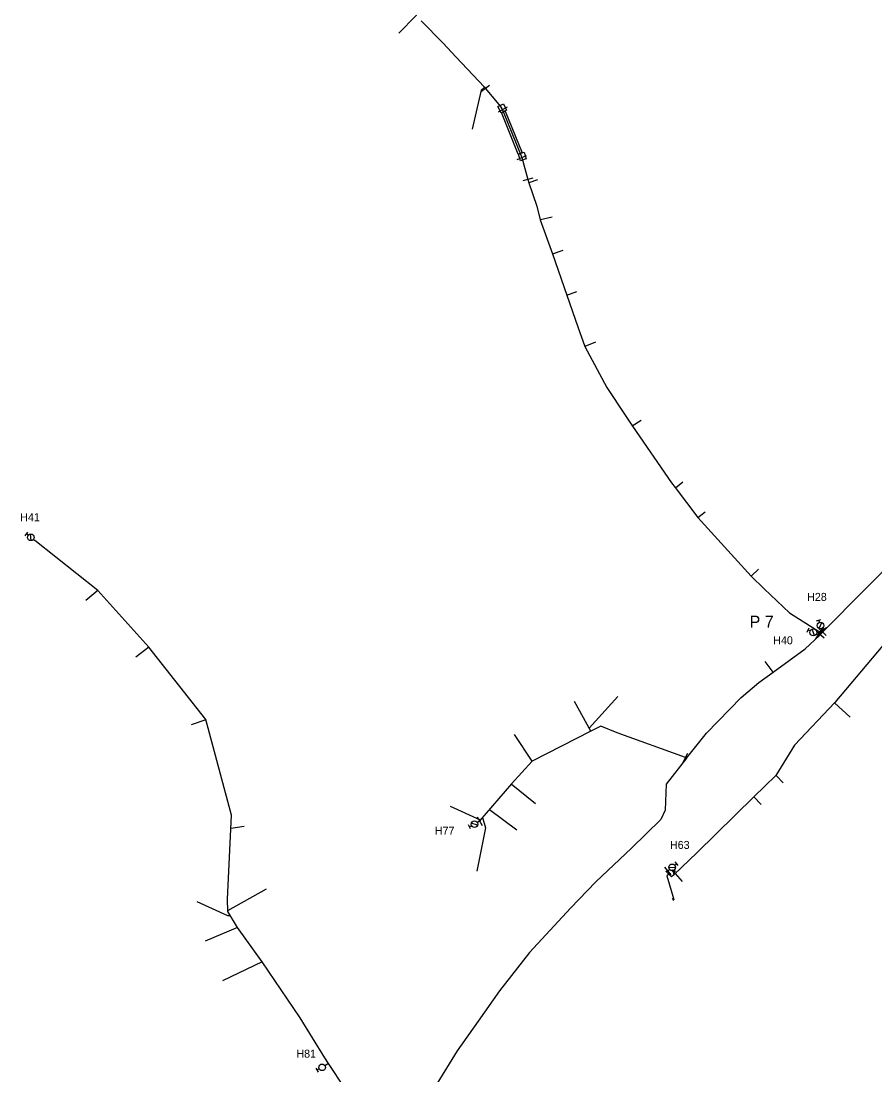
# Model space of a CAD drawing. Extents: x -548873 to -538270, y -1201997 to -1192514.
# Drawn here: x -547520.2 to -547306.8, y -1195753.9 to -1195490.5 of the extents above; entities that cross this region are included whole.
import ezdxf

# ---------------------------------------------------------------- set-up
doc = ezdxf.new("R2010")
doc.units = 0
for name, color, linetype in [('KN_HRAN_STÁTNÍ', 7, 'Continuous'), ('KN_PARC_Č', 7, 'Continuous'), ('KN_VKP_HRAN_SPORNÁ', 7, 'Continuous'), ('PK_PARC_Čv', 7, 'Continuous'), ('Vrstva 29', 7, 'Continuous'), ('Vrstva 37', 7, 'Continuous'), ('Vrstva 39', 7, 'Continuous')]:
    doc.layers.add(name, color=color, linetype=linetype)

# ---------------------------------------------------------------- blocks, each defined once
blk = doc.blocks.new('160')
at = {"layer": 'KN_HRAN_STÁTNÍ'}
blk.add_circle((0, 0), 0.0458, dxfattribs=at)
blk = doc.blocks.new('147')
at = {"layer": 'KN_HRAN_STÁTNÍ'}
blk.add_line((0, 1.27), (0, -1.27), dxfattribs=at)
blk = doc.blocks.new('133')
at = {"layer": 'KN_HRAN_STÁTNÍ'}
for p, q in [((0.28, 0), (0, 0)), ((0.54, 0.58), (1.7, -0.58)), ((1.94, 0), (2.52, 0)), ((2.52, 0.58), (2.52, -0.58))]:
    blk.add_line(p, q, dxfattribs=at)
blk.add_circle((1.11, 0), 0.825, dxfattribs=at)
blk = doc.blocks.new('132')
at = {"layer": 'KN_HRAN_STÁTNÍ'}
for p, q in [((0.3, 0), (0, 0)), ((1.96, 0), (2.52, 0)), ((2.52, 0.58), (2.52, -0.58))]:
    blk.add_line(p, q, dxfattribs=at)
blk.add_circle((1.13, 0.01), 0.825, dxfattribs=at)
blk = doc.blocks.new('150')
at = {"layer": 'KN_HRAN_STÁTNÍ'}
blk.add_line((0, 1.27), (0, -1.27), dxfattribs=at)
blk = doc.blocks.new('128')
at = {"layer": 'KN_HRAN_STÁTNÍ'}
for p, q in [((-0.19, 1.06), (-0.43, 1.15)), ((-0.36, 0.84), (-0.19, 1.06)), ((-0.19, 1.06), (-0.02, 1.25)), ((-0.19, 1.06), (0, 0)), ((0.05, 0.95), (-0.19, 1.06)), ((-0.1, 1), (0.41, 0.91)), ((-0.07, 0.82), (0.17, 0.96)), ((0.17, 0.96), (-0.02, 1.13)), ((0.17, 0.96), (0, 0)), ((0.19, 1.21), (0.17, 0.96)), ((0.17, 0.96), (0.38, 1.08)), ((0.36, 0.77), (0.17, 0.96))]:
    blk.add_line(p, q, dxfattribs=at)

msp = doc.modelspace()

# ---------------------------------------------------------------- linework, layer by layer
at = {"layer": 'KN_PARC_Č'}
for points in [[(-547421.368, -1195489.122), (-547421.49, -1195489.23), (-547425.759, -1195493.564)], [(-547404.348, -1195507.003), (-547404.44, -1195507.09), (-547405.167, -1195507.776), (-547407.449, -1195517.535)], [(-547393.308, -1195530.92), (-547393.19, -1195530.89), (-547391.015, -1195530.156)], [(-547390.473, -1195540.168), (-547390.35, -1195540.14), (-547387.475, -1195539.42)], [(-547387.323, -1195548.662), (-547384.692, -1195547.782)], [(-547383.738, -1195558.995), (-547381.305, -1195558.142)], [(-547379.307, -1195571.831), (-547379.16, -1195571.78), (-547376.533, -1195570.701)], [(-547367.407, -1195591.73), (-547365.218, -1195590.303)], [(-547356.654, -1195607.161), (-547354.823, -1195605.7)], [(-547351.028, -1195614.592), (-547349.206, -1195613.219)], [(-547337.739, -1195629.251), (-547335.853, -1195627.531)], [(-547500.975, -1195632.852), (-547504.001, -1195635.361)], [(-547488.22, -1195647.052), (-547491.504, -1195649.479)], [(-547332.224, -1195653.223), (-547334.189, -1195650.617)], [(-547377.778, -1195668.026), (-547381.876, -1195660.553)], [(-547378.208, -1195667.242), (-547371.04, -1195659.312)], [(-547316.9, -1195660.93), (-547312.995, -1195664.495)], [(-547474.007, -1195665.163), (-547477.666, -1195666.391)], [(-547392.404, -1195675.474), (-547396.862, -1195668.814)], [(-547331.495, -1195679.06), (-547329.695, -1195680.901)], [(-547397.645, -1195681.202), (-547391.615, -1195686.121)], [(-547337.038, -1195684.445), (-547335.245, -1195686.308)], [(-547405.354, -1195690.223), (-547412.826, -1195686.829)], [(-547404.824, -1195689.603), (-547404.093, -1195692.207), (-547406.29, -1195702.973)], [(-547403.128, -1195687.618), (-547396.236, -1195692.664)], [(-547467.746, -1195692.252), (-547464.4, -1195691.77)], [(-547358.294, -1195703.731), (-547358.766, -1195704.195), (-547357.002, -1195710.113)], [(-547356.708, -1195703.598), (-547354.916, -1195705.609)], [(-547468.498, -1195712.843), (-547458.817, -1195707.457)], [(-547467.871, -1195714.136), (-547468.499, -1195714.186), (-547476.15, -1195710.63)], [(-547357.124, -1195709.705), (-547357.491, -1195710.009)], [(-547357.066, -1195709.898), (-547357.278, -1195710.35)], [(-547466.059, -1195717.114), (-547474.163, -1195720.528)], [(-547459.879, -1195725.68), (-547469.82, -1195730.418)]]:
    msp.add_lwpolyline(points, dxfattribs=at)
at = {"layer": 'KN_VKP_HRAN_SPORNÁ'}
for points in [[(-547420.18, -1195490.46), (-547414.68, -1195496.05), (-547411.499, -1195499.421), (-547404.35, -1195507), (-547404.08, -1195507.37)], [(-547404.08, -1195507.37), (-547400.46, -1195511.78), (-547399.83, -1195512.67)], [(-547399.83, -1195512.67), (-547396.278, -1195521.521), (-547395.03, -1195524.63)], [(-547395.03, -1195524.63), (-547393.52, -1195530.09)], [(-547393.52, -1195530.09), (-547393.3, -1195530.95), (-547391.26, -1195536.75), (-547390.47, -1195540.18), (-547387.32, -1195548.67), (-547383.74, -1195558.99), (-547380.993, -1195566.947), (-547379.3, -1195571.85), (-547373.75, -1195582.08), (-547369.199, -1195589.003), (-547367.4, -1195591.74), (-547357.64, -1195605.93), (-547356.67, -1195607.14), (-547351.03, -1195614.59), (-547343.58, -1195622.85), (-547337.74, -1195629.25), (-547334.43, -1195632.46), (-547328.16, -1195638.43), (-547321.548, -1195642.574), (-547320.39, -1195643.3)], [(-547241.246, -1195569.957), (-547259.588, -1195592.568), (-547270.51, -1195606.032), (-547278.725, -1195615.639), (-547291.147, -1195630.416), (-547304.795, -1195646.608), (-547316.823, -1195660.848), (-547326.873, -1195671.491), (-547331.512, -1195679.088), (-547337.016, -1195684.424), (-547351.223, -1195698.329), (-547357.069, -1195703.944)], [(-547319.87, -1195643.25), (-547319.38, -1195642.78), (-547300.1, -1195623.31), (-547296.04, -1195618.93), (-547293.43, -1195615.64)], [(-547425.785, -1195772.759), (-547433.342, -1195767.71), (-547439.235, -1195757.255), (-547443.312, -1195751.099), (-547444.279, -1195749.64), (-547450.389, -1195739.691), (-547459.879, -1195725.68), (-547466.059, -1195717.114), (-547468.493, -1195713.113), (-547468.55, -1195710.024), (-547467.599, -1195689.001), (-547474.02, -1195665.116), (-547488.253, -1195647.01), (-547500.937, -1195632.883), (-547516.701, -1195620.349), (-547516.745, -1195620.314)], [(-547353.907, -1195674.777), (-547348.862, -1195668.535), (-547340.213, -1195659.581), (-547335.828, -1195655.833), (-547332.223, -1195653.222), (-547324.245, -1195647.444), (-547320.669, -1195644.126), (-547320.44, -1195643.86)], [(-547320.44, -1195643.86), (-547320.091, -1195643.487)], [(-547320.39, -1195643.3), (-547320.091, -1195643.487)], [(-547320.091, -1195643.487), (-547319.87, -1195643.25)], [(-547354.157, -1195674.632), (-547371.167, -1195668.434), (-547375.271, -1195666.75), (-547377.778, -1195668.026), (-547392.405, -1195675.475), (-547392.427, -1195675.486), (-547397.637, -1195681.193), (-547405.479, -1195690.369)], [(-547353.907, -1195674.777), (-547358.947, -1195681.231), (-547359.171, -1195687.793), (-547360.282, -1195690.048), (-547367.646, -1195697.265), (-547376.495, -1195705.645), (-547382.898, -1195712.235), (-547393.089, -1195723.345), (-547400.573, -1195732.935), (-547405.899, -1195740.503), (-547411.174, -1195747.949), (-547417.586, -1195758.304), (-547425.386, -1195772.82)], [(-547353.907, -1195674.777), (-547354.157, -1195674.632)], [(-547357.069, -1195703.944), (-547357.605, -1195704.459), (-547358.916, -1195703.075)]]:
    msp.add_lwpolyline(points, dxfattribs=at)
at = {"layer": 'PK_PARC_Čv'}
for points in [[(-547400.978, -1195511.838), (-547399.63, -1195511.18), (-547398.83, -1195512.82), (-547400.178, -1195513.478), (-547400.978, -1195511.838)], [(-547395.876, -1195523.767), (-547394.45, -1195523.3), (-547393.9, -1195524.98), (-547395.326, -1195525.447), (-547395.876, -1195523.767)], [(-547516.745, -1195620.314), (-547516.825, -1195620.25)], [(-547319.711, -1195643.098), (-547319.93, -1195642.87), (-547320.01, -1195642.63)], [(-547320.67, -1195644.127), (-547320.906, -1195643.864), (-547321.12, -1195643.784)], [(-547405.479, -1195690.369), (-547405.554, -1195690.502), (-547405.899, -1195690.693)], [(-547358.819, -1195703.177), (-547358.31, -1195702.755)], [(-547443.312, -1195751.099), (-547443.972, -1195751.466)]]:
    msp.add_lwpolyline(points, dxfattribs=at)
at = {"layer": 'Vrstva 37'}
msp.add_lwpolyline([(-547399.152, -1195513.017), (-547394.97, -1195523.436), (-547395.898, -1195523.808), (-547400.08, -1195513.389), (-547399.152, -1195513.017)], dxfattribs=at)

# ---------------------------------------------------------------- block references
at = {"layer": 'PK_PARC_Čv'}
for name, p, xscale, yscale, rotation in [('133', (-547516.825, -1195620.25), 1.000000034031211, 1.0000000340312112, 141.99999959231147), ('133', (-547320.01, -1195642.63), 0.999999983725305, 0.999999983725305, 109.00000122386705), ('133', (-547321.12, -1195643.784), 1.0296949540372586, 1.0296949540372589, 155.86620948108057), ('150', (-547320.906, -1195643.864), 0.9999999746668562, 0.999999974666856, -34.00000045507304), ('150', (-547319.93, -1195642.87), 0.9999999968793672, 0.9999999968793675, -57.99999972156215), ('133', (-547405.899, -1195690.693), 1.0037042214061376, 1.0037042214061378, -150.62079160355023), ('150', (-547405.555, -1195690.503), 1.0037042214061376, 1.0037042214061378, 29.379208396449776), ('133', (-547358.31, -1195702.755), 1.0000000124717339, 1.0000000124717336, 40.00000131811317), ('150', (-547358.581, -1195702.98), 1.0000000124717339, 1.0000000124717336, 40.00000131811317), ('132', (-547443.972, -1195751.466), 0.9999999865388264, 0.9999999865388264, -149.99999955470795)]:
    msp.add_blockref(name, p, dxfattribs=dict(at, xscale=xscale, yscale=yscale, rotation=rotation))
at = {"layer": 'Vrstva 29'}
for name, p, xscale, yscale, rotation in [('147', (-547404.08, -1195507.37), 1.000000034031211, 1.0000000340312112, -51.999999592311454), ('147', (-547399.83, -1195512.67), 1.0000000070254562, 1.0000000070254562, -61.000001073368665), ('147', (-547395.03, -1195524.63), 1.0000000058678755, 1.0000000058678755, 111.99999900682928), ('147', (-547393.52, -1195530.09), 0.999999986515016, 0.9999999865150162, -74.99999987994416), ('160', (-547516.745, -1195620.314), 1.000000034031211, 1.0000000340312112, -38.000000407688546), ('147', (-547320.39, -1195643.3), 0.9999999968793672, 0.9999999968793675, -32.00000027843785), ('147', (-547319.87, -1195643.25), 1.0000000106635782, 1.0000000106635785, 45.99999834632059), ('147', (-547320.44, -1195643.86), 1.0000000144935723, 1.0000000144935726, 49.00000089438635), ('160', (-547320.091, -1195643.487), 1.0092050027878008, 1.0092050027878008, 11.116918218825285), ('147', (-547354.157, -1195674.632), 1.0169562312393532, 1.016956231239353, 153.02398354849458), ('160', (-547353.907, -1195674.777), 1.0060666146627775, 1.0060666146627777, 12.654735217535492), ('160', (-547405.479, -1195690.369), 1.0000000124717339, 1.0000000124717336, 49.99999868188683), ('160', (-547358.916, -1195703.075), 1.0000000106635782, 1.0000000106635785, 134.00000165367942), ('160', (-547357.069, -1195703.944), 1.0000000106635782, 1.0000000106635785, -135.99999834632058)]:
    msp.add_blockref(name, p, dxfattribs=dict(at, xscale=xscale, yscale=yscale, rotation=rotation))
at = {"layer": 'Vrstva 39'}
msp.add_blockref('128', (-547357.069, -1195703.944), dxfattribs=at)

# ---------------------------------------------------------------- texts
at = {"layer": 'PK_PARC_Čv'}
for s, height, p in [('H41', 2, (-547520.377, -1195615.528)), ('H28', 2, (-547323.72, -1195635.45)), ('P 7', 3, (-547338.11, -1195642.154)), ('H40', 2, (-547332.2, -1195646.294)), ('H77', 2, (-547416.759, -1195693.903)), ('H63', 2, (-547358, -1195697.445)), ('H81', 2, (-547451.362, -1195749.626))]:
    msp.add_text(s, height=height, dxfattribs=at).set_placement(p)

doc.saveas('drawing.dxf')
